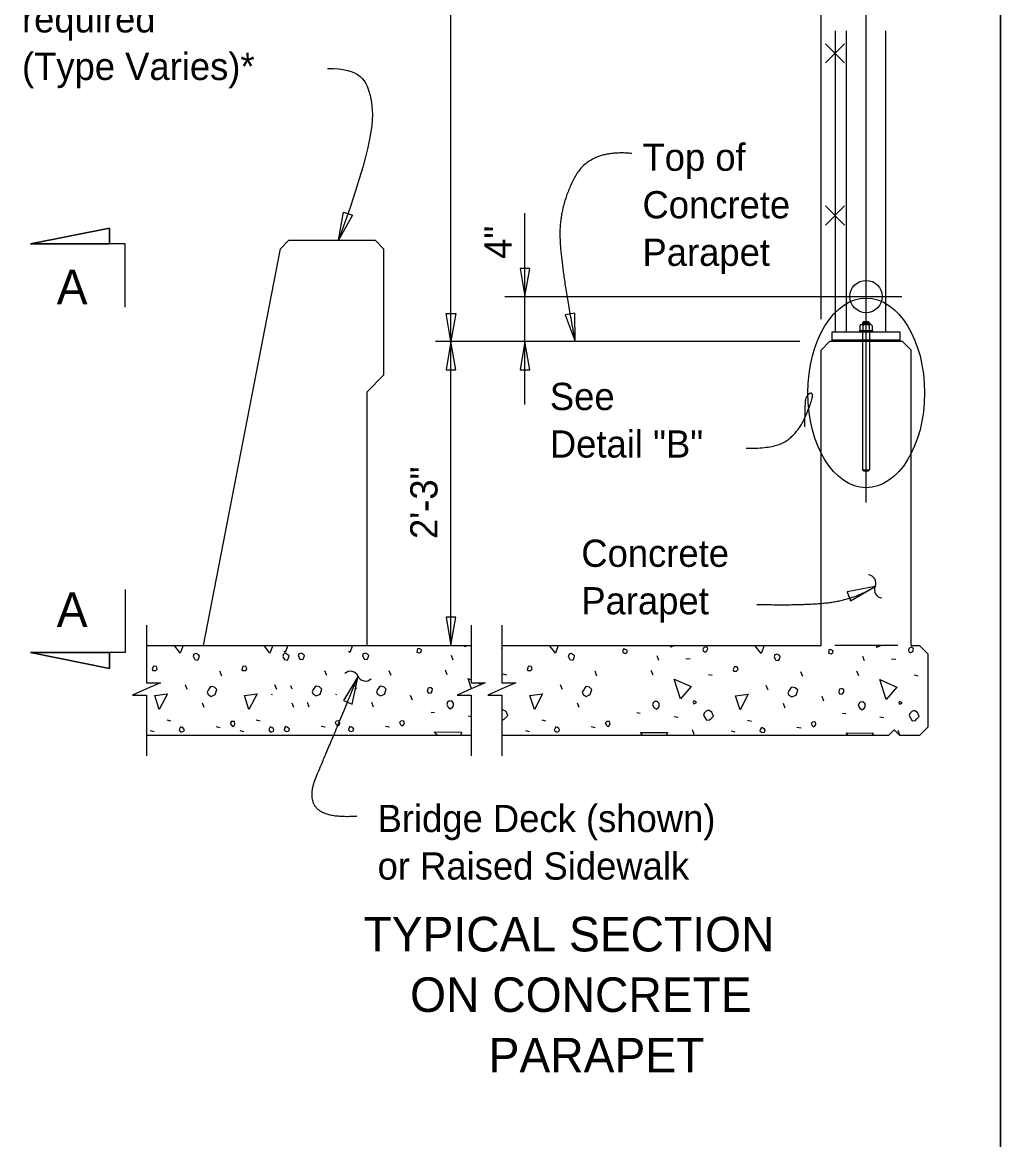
# Model space of a CAD drawing. Extents: x 0 to 41.1, y 0 to 25.9.
# Drawn here: x 33.8 to 41.05, y 10.57 to 18.84 of the extents above; entities that cross this region are included whole.
import ezdxf

# ---------------------------------------------------------------- set-up
doc = ezdxf.new("R2010")
doc.units = 0
for name, color, linetype in [('ActivePts-ConstElements', 7, 'Continuous'), ('CL_Major', 7, 'Continuous'), ('Dimension', 7, 'Continuous'), ('Miscellaneous', 7, 'Continuous'), ('Miscellaneous1', 7, 'Continuous'), ('SteelMisc', 7, 'Continuous'), ('SteelMisc_h', 7, 'Continuous'), ('SupstrConc', 7, 'Continuous'), ('SupstrConc_h', 7, 'Continuous'), ('TextStructures', 7, 'Continuous')]:
    doc.layers.add(name, color=color, linetype=linetype)

# ---------------------------------------------------------------- blocks, each defined once
blk = doc.blocks.new('Terminator-Arrow')
at = {"layer": 'Dimension'}
blk.add_lwpolyline([(0, 0), (-0.00041, 0.000069), (-0.00041, -0.000069), (0, 0)], dxfattribs=at)
blk.add_lwpolyline([(0, 0), (-0.00041, 0.000069), (-0.00041, -0.000069)], close=True, dxfattribs=at)

msp = doc.modelspace()

# ---------------------------------------------------------------- linework, layer by layer
at = {"layer": 'ActivePts-ConstElements'}
msp.add_lwpolyline([(0, 0), (41.0506, 0), (41.0506, 25.9461), (0, 25.9461)], close=True, dxfattribs=at)
at = {"layer": 'CL_Major'}
for p, q in [((40.0537, 15.2829), (40.0537, 19.5023)), ((37.3776, 16.8078), (40.3194, 16.8078))]:
    msp.add_line(p, q, dxfattribs=at)
at = {"layer": 'Dimension'}
for p, q in [((36.9797, 14.2246), (36.9797, 22.8079)), ((39.7204, 16.6402), (39.7204, 19.0859)), ((37.5276, 16.0092), (37.5276, 17.4261)), ((33.8643, 17.1974), (34.4503, 17.3146)), ((34.4503, 17.3146), (34.4503, 17.1974)), ((34.5675, 17.1974), (33.8643, 17.1974)), ((34.5675, 16.7286), (34.5675, 17.1974)), ((40.0537, 16.5552), (40.0537, 16.5545)), ((39.5643, 16.4746), (36.8659, 16.4746)), ((34.5675, 14.6399), (34.5675, 14.1711)), ((34.5675, 14.1711), (33.8643, 14.1711)), ((33.8643, 14.1711), (34.4503, 14.0539)), ((34.4503, 14.0539), (34.4503, 14.1711))]:
    msp.add_line(p, q, dxfattribs=at)
for points in [[(34.4503, 17.1974), (34.4503, 17.3146), (33.8643, 17.1974)], [(37.5276, 16.8079), (37.5629, 17.0161), (37.4923, 17.0161)], [(36.9797, 16.4746), (36.9444, 16.6828), (37.015, 16.6828)], [(37.8983, 16.4746), (37.8958, 16.6858), (37.8263, 16.6731)], [(36.9797, 16.4746), (36.9444, 16.2663), (37.015, 16.2663)], [(37.5276, 16.4746), (37.4923, 16.2663), (37.5629, 16.2663)], [(40.1214, 14.6607), (39.9139, 14.6211), (39.9386, 14.5549)], [(36.9797, 14.2246), (37.015, 14.4328), (36.9444, 14.4328)], [(34.4503, 14.1711), (34.4503, 14.0539), (33.8643, 14.1711)], [(36.2916, 13.9969), (36.1831, 13.8157), (36.2488, 13.79)]]:
    msp.add_lwpolyline(points, close=True, dxfattribs=at)
for points in [[(34.7238, 14.3746), (34.7238, 13.9474), (34.8272, 13.9474), (34.7238, 13.9024), (34.6205, 13.8574), (34.7238, 13.8574), (34.7238, 13.4079)], [(37.1296, 14.3746), (37.1296, 13.9474), (37.233, 13.9474), (37.1296, 13.9024), (37.0263, 13.8574), (37.1296, 13.8574), (37.1296, 13.4079)], [(37.3569, 14.3746), (37.3569, 13.9474), (37.4602, 13.9474), (37.3569, 13.9024), (37.2536, 13.8574), (37.3569, 13.8574), (37.3569, 13.4079)]]:
    msp.add_lwpolyline(points, dxfattribs=at)
for centre, start, end in [((40.0672, 14.6869), 334.61622, 86.34344), ((40.1749, 14.6358), 154.61622, 266.34344), ((36.236, 13.9739), 22.88008, 134.6073), ((36.3458, 14.0202), 202.88008, 314.6073)]:
    msp.add_arc(centre, 0.0596, start, end, dxfattribs=at)
msp.add_ellipse((40.055, 16.0943), major_axis=(0, 0.7024), ratio=0.61552, dxfattribs=at)
for points, degree in [([(36.0647, 18.496), (36.3065, 18.5019), (36.4127, 18.3129), (36.4127, 17.9586), (36.1473, 17.2245)], 3), ([(38.3183, 17.8669), (38.0045, 17.8975), (37.7862, 17.4818), (37.7862, 17.0625), (37.8983, 16.4745)], 2), ([(39.1649, 15.6846), (39.3915, 15.6806), (39.562, 15.8155), (39.6571, 16.0457), (39.6571, 16.0974), (39.6199, 16.0825), (39.5976, 16.0298), (39.599, 15.843)], 2), ([(39.246, 14.5284), (39.5846, 14.5201), (39.9562, 14.5615), (40.1214, 14.6607)], 2), ([(36.2826, 12.9596), (36.0506, 12.9429), (35.9147, 13.1019), (36.0652, 13.445), (36.2916, 13.9969)], 2)]:
    msp.add_open_spline(points, degree=degree, dxfattribs=at)
at = {"layer": 'Miscellaneous'}
for p, q in [((39.8952, 18.6785), (39.7538, 18.5373)), ((39.7538, 18.6785), (39.8952, 18.5373)), ((39.8952, 17.4785), (39.7538, 17.3373)), ((39.7538, 17.4785), (39.8952, 17.3373)), ((40.0425, 16.6169), (40.0633, 16.6169)), ((40.0425, 16.6072), (40.0633, 16.6072)), ((39.8037, 16.4815), (40.3037, 16.4815)), ((39.8037, 16.478), (40.3037, 16.478)), ((35.3909, 14.2246), (35.3923, 14.2243)), ((36.9947, 14.1164), (36.9824, 14.15)), ((38.169, 14.2246), (38.1703, 14.2243)), ((38.5186, 14.1129), (38.5062, 14.1465)), ((39.6751, 14.2246), (39.6941, 14.2207)), ((38.7183, 14.1288), (38.7501, 14.1253)), ((40.0424, 14.1094), (40.03, 14.143)), ((40.2421, 14.1253), (40.274, 14.1218)), ((35.2827, 13.998), (35.2685, 14.0334)), ((36.0602, 14.0015), (36.0461, 14.0369)), ((36.5369, 14.0015), (36.5228, 14.0369)), ((36.9523, 14.0068), (36.9382, 14.0422)), ((37.3624, 14.0139), (37.3907, 14.0068)), ((38.0607, 13.998), (38.0466, 14.0334)), ((38.4761, 14.0033), (38.462, 14.0387)), ((38.8863, 14.0104), (38.9145, 14.0033)), ((39.5845, 13.9945), (39.5704, 14.0298)), ((39.9999, 13.9998), (39.9858, 14.0351)), ((40.4101, 14.0068), (40.4384, 13.9998)), ((35.0263, 13.8972), (35.0122, 13.9326)), ((35.6898, 13.8972), (35.6757, 13.9326)), ((35.8039, 13.9008), (35.7944, 13.9245)), ((36.2806, 13.9008), (36.2711, 13.9245)), ((37.8044, 13.8972), (37.7902, 13.9326)), ((39.3282, 13.8937), (39.3141, 13.9291)), ((36.6942, 13.8195), (36.6801, 13.8548)), ((39.7419, 13.8124), (39.7277, 13.8477)), ((35.1519, 13.7647), (35.1395, 13.7983)), ((35.8154, 13.7647), (35.803, 13.7983)), ((35.9294, 13.7682), (35.917, 13.8018)), ((36.4061, 13.7682), (36.3937, 13.8018)), ((37.9299, 13.7647), (37.9175, 13.7983)), ((39.4537, 13.7611), (39.4413, 13.7947)), ((34.8743, 13.6745), (34.9026, 13.6674)), ((35.5378, 13.6745), (35.5661, 13.6674)), ((36.8321, 13.7311), (36.8569, 13.7275)), ((37.1079, 13.7028), (37.1296, 13.699)), ((37.6524, 13.6745), (37.6806, 13.6674)), ((38.3559, 13.7275), (38.3807, 13.724)), ((38.6317, 13.6993), (38.6617, 13.694)), ((39.1762, 13.671), (39.2045, 13.6639)), ((39.8797, 13.724), (39.9045, 13.7205)), ((40.1555, 13.6957), (40.1856, 13.6904)), ((34.7523, 13.595), (34.7806, 13.5879)), ((35.2402, 13.6232), (35.2703, 13.6179)), ((35.4158, 13.595), (35.4441, 13.5879)), ((36.0178, 13.6268), (36.0478, 13.6215)), ((36.4945, 13.6268), (36.5245, 13.6215)), ((37.5304, 13.595), (37.5587, 13.5879)), ((38.0183, 13.6232), (38.0483, 13.6179)), ((38.7802, 13.5649), (38.7678, 13.5985)), ((39.0542, 13.5914), (39.0825, 13.5844)), ((39.5421, 13.6197), (39.5721, 13.6144)), ((40.304, 13.5614), (40.2916, 13.595))]:
    msp.add_line(p, q, dxfattribs=at)
for points in [[(39.8246, 18.7753), (39.8246, 16.5475)], [(34.9751, 14.1677), (34.9319, 14.2246)], [(34.9963, 14.2246), (34.9751, 14.1677)], [(35.0741, 14.1359), (35.0829, 14.12), (35.1041, 14.1164), (35.113, 14.1324), (35.1165, 14.1465), (35.1077, 14.1553), (35.0918, 14.1642), (35.0758, 14.1589), (35.0705, 14.143), (35.0741, 14.1359)], [(35.6386, 14.1677), (35.5954, 14.2246)], [(35.6598, 14.2246), (35.6386, 14.1677)], [(35.7376, 14.1359), (35.7464, 14.12), (35.7676, 14.1164), (35.7765, 14.1324), (35.78, 14.1465), (35.7712, 14.1553), (35.7553, 14.1642), (35.7393, 14.1589), (35.734, 14.143), (35.7376, 14.1359)], [(35.7526, 14.1713), (35.7438, 14.1829)], [(35.7725, 14.2246), (35.7526, 14.1713)], [(35.8516, 14.1394), (35.8605, 14.1235), (35.8817, 14.12), (35.8905, 14.1359), (35.894, 14.15), (35.8852, 14.1589), (35.8693, 14.1677), (35.8534, 14.1624), (35.8481, 14.1465), (35.8516, 14.1394)], [(36.2293, 14.1713), (36.2205, 14.1829)], [(36.2492, 14.2246), (36.2293, 14.1713)], [(36.3283, 14.1394), (36.3371, 14.1235), (36.3584, 14.12), (36.3672, 14.1359), (36.3707, 14.15), (36.3619, 14.1589), (36.346, 14.1677), (36.3301, 14.1624), (36.3248, 14.1465), (36.3283, 14.1394)], [(36.7278, 14.1748), (36.7473, 14.1695), (36.7596, 14.1783), (36.7614, 14.1907), (36.7579, 14.1942), (36.7437, 14.2013), (36.7314, 14.1995), (36.7296, 14.1872), (36.7278, 14.1748)], [(37.0831, 14.2154), (37.0859, 14.2246)], [(37.1034, 14.2246), (37.0831, 14.2154)], [(37.3569, 14.2024), (37.3571, 14.2031), (37.3569, 14.2043)], [(37.7531, 14.1677), (37.7099, 14.2246)], [(37.7744, 14.2246), (37.7531, 14.1677)], [(37.8521, 14.1359), (37.861, 14.12), (37.8822, 14.1164), (37.891, 14.1324), (37.8945, 14.1465), (37.8857, 14.1553), (37.8698, 14.1642), (37.8539, 14.1589), (37.8486, 14.143), (37.8521, 14.1359)], [(38.2516, 14.1713), (38.2711, 14.1659), (38.2834, 14.1748), (38.2852, 14.1872), (38.2817, 14.1907), (38.2675, 14.1978), (38.2552, 14.196), (38.2534, 14.1836), (38.2516, 14.1713)], [(38.6069, 14.2119), (38.6108, 14.2246)], [(38.6351, 14.2246), (38.6069, 14.2119)], [(38.8544, 14.1766), (38.8615, 14.1766), (38.8756, 14.1836), (38.881, 14.1995), (38.8792, 14.2084), (38.865, 14.2154), (38.8474, 14.2048), (38.8438, 14.1942), (38.8474, 14.1836), (38.8544, 14.1766)], [(39.2769, 14.1642), (39.231, 14.2246)], [(39.2995, 14.2246), (39.2769, 14.1642)], [(39.3759, 14.1324), (39.3848, 14.1164), (39.406, 14.1129), (39.4148, 14.1288), (39.4184, 14.143), (39.4095, 14.1518), (39.3936, 14.1606), (39.3777, 14.1553), (39.3724, 14.1394), (39.3759, 14.1324)], [(39.7754, 14.1677), (39.7949, 14.1624), (39.8073, 14.1713), (39.809, 14.1836), (39.8055, 14.1872), (39.7914, 14.1942), (39.779, 14.1925), (39.7772, 14.1801), (39.7754, 14.1677)], [(40.1308, 14.2084), (40.1357, 14.2246)], [(40.1668, 14.2246), (40.1308, 14.2084)], [(40.3782, 14.173), (40.3853, 14.173), (40.3995, 14.1801), (40.4048, 14.196), (40.403, 14.2048), (40.3889, 14.2119), (40.3712, 14.2013), (40.3676, 14.1907), (40.3712, 14.1801), (40.3782, 14.173)], [(34.7718, 14.0387), (34.793, 14.0387), (34.8036, 14.0493), (34.7983, 14.0687), (34.7753, 14.0705), (34.7718, 14.0599), (34.7665, 14.051), (34.7718, 14.0387), (34.7683, 14.0422)], [(35.4353, 14.0387), (35.4565, 14.0387), (35.4671, 14.0493), (35.4618, 14.0687), (35.4388, 14.0705), (35.4353, 14.0599), (35.43, 14.051), (35.4353, 14.0387), (35.4318, 14.0422)], [(37.5498, 14.0387), (37.571, 14.0387), (37.5816, 14.0493), (37.5763, 14.0687), (37.5534, 14.0705), (37.5498, 14.0599), (37.5445, 14.051), (37.5498, 14.0387), (37.5463, 14.0422)], [(39.0736, 14.0351), (39.0949, 14.0351), (39.1055, 14.0457), (39.1002, 14.0652), (39.0772, 14.067), (39.0736, 14.0563), (39.0683, 14.0475), (39.0736, 14.0351), (39.0701, 14.0387)], [(35.1801, 13.8601), (35.2031, 13.8477), (35.2332, 13.8601), (35.2455, 13.8972), (35.2279, 13.9149), (35.2049, 13.9202), (35.1943, 13.9132), (35.1819, 13.8937), (35.1731, 13.8778), (35.1801, 13.8601)], [(35.9577, 13.8637), (35.9807, 13.8513), (36.0107, 13.8637), (36.0231, 13.9008), (36.0054, 13.9185), (35.9824, 13.9238), (35.9718, 13.9167), (35.9594, 13.8972), (35.9506, 13.8813), (35.9577, 13.8637)], [(36.4344, 13.8637), (36.4573, 13.8513), (36.4874, 13.8637), (36.4998, 13.9008), (36.4821, 13.9185), (36.4591, 13.9238), (36.4485, 13.9167), (36.4361, 13.8972), (36.4273, 13.8813), (36.4344, 13.8637)], [(36.8038, 13.8866), (36.8127, 13.8707), (36.8321, 13.8725), (36.841, 13.8849), (36.8427, 13.9043), (36.8303, 13.9096), (36.8215, 13.9114), (36.8109, 13.9079), (36.8074, 13.9043), (36.8038, 13.8866)], [(37.1323, 13.9036), (37.1079, 13.9786), (37.1296, 13.9691)], [(37.1792, 13.9474), (37.206, 13.9357)], [(37.9582, 13.8601), (37.9812, 13.8477), (38.0112, 13.8601), (38.0236, 13.8972), (38.0059, 13.9149), (37.9829, 13.9202), (37.9723, 13.9132), (37.9599, 13.8937), (37.9511, 13.8778), (37.9582, 13.8601)], [(38.6794, 13.8283), (38.6317, 13.975), (38.7572, 13.9202), (38.6794, 13.8283)], [(39.482, 13.8566), (39.505, 13.8442), (39.535, 13.8566), (39.5474, 13.8937), (39.5297, 13.9114), (39.5067, 13.9167), (39.4961, 13.9096), (39.4838, 13.8902), (39.4749, 13.8743), (39.482, 13.8566)], [(39.8515, 13.8796), (39.8603, 13.8637), (39.8797, 13.8654), (39.8886, 13.8778), (39.8903, 13.8972), (39.878, 13.9025), (39.8691, 13.9043), (39.8585, 13.9008), (39.855, 13.8972), (39.8515, 13.8796)], [(40.2032, 13.8248), (40.1555, 13.9715), (40.281, 13.9167), (40.2032, 13.8248)], [(34.8195, 13.7505), (34.7859, 13.8548), (34.8796, 13.8672), (34.8195, 13.7505)], [(35.483, 13.7505), (35.4494, 13.8548), (35.5431, 13.8672), (35.483, 13.7505)], [(35.6532, 13.863), (35.6503, 13.8574)], [(36.1298, 13.863), (36.127, 13.8574)], [(37.5976, 13.7505), (37.564, 13.8548), (37.6577, 13.8672), (37.5976, 13.7505)], [(39.1214, 13.747), (39.0878, 13.8513), (39.1815, 13.8637), (39.1214, 13.747)], [(36.9488, 13.7876), (36.9594, 13.7664), (36.9771, 13.7558), (36.9912, 13.7664), (36.9983, 13.777), (36.9983, 13.7983), (36.9824, 13.8142), (36.9629, 13.8124), (36.9541, 13.8036), (36.9488, 13.7876)], [(37.3569, 13.6752), (37.3713, 13.6763), (37.3801, 13.6851), (37.3996, 13.7046), (37.3872, 13.7346), (37.3624, 13.7488), (37.3569, 13.7465)], [(38.4726, 13.7841), (38.4832, 13.7629), (38.5009, 13.7523), (38.515, 13.7629), (38.5221, 13.7735), (38.5221, 13.7947), (38.5062, 13.8106), (38.4867, 13.8089), (38.4779, 13.8), (38.4726, 13.7841)], [(38.7784, 13.7929), (38.7979, 13.8018), (38.7908, 13.8089), (38.7784, 13.8142), (38.7731, 13.8018), (38.7784, 13.7929)], [(38.8491, 13.7081), (38.8721, 13.671), (38.8951, 13.6727), (38.9039, 13.6816), (38.9234, 13.701), (38.911, 13.7311), (38.8863, 13.7452), (38.8686, 13.7381), (38.8544, 13.724), (38.8491, 13.7081)], [(39.9964, 13.7806), (40.007, 13.7594), (40.0247, 13.7488), (40.0388, 13.7594), (40.0459, 13.77), (40.0459, 13.7912), (40.03, 13.8071), (40.0106, 13.8053), (40.0017, 13.7965), (39.9964, 13.7806)], [(40.3022, 13.7894), (40.3217, 13.7983), (40.3146, 13.8053), (40.3022, 13.8106), (40.2969, 13.7983), (40.3022, 13.7894)], [(40.3729, 13.7046), (40.3959, 13.6674), (40.4189, 13.6692), (40.4277, 13.678), (40.4472, 13.6975), (40.4348, 13.7275), (40.4101, 13.7417), (40.3924, 13.7346), (40.3782, 13.7205), (40.3729, 13.7046)], [(35.3516, 13.6356), (35.3622, 13.625), (35.3728, 13.6321), (35.3799, 13.6427), (35.3764, 13.6604), (35.3675, 13.6621), (35.3551, 13.6604), (35.3445, 13.6498), (35.3516, 13.6356)], [(36.1292, 13.6392), (36.1398, 13.6285), (36.1504, 13.6356), (36.1574, 13.6462), (36.1539, 13.6639), (36.1451, 13.6657), (36.1327, 13.6639), (36.1221, 13.6533), (36.1292, 13.6392)], [(36.6058, 13.6392), (36.6164, 13.6285), (36.6271, 13.6356), (36.6341, 13.6462), (36.6306, 13.6639), (36.6218, 13.6657), (36.6094, 13.6639), (36.5988, 13.6533), (36.6058, 13.6392)], [(38.1297, 13.6356), (38.1403, 13.625), (38.1509, 13.6321), (38.1579, 13.6427), (38.1544, 13.6604), (38.1456, 13.6621), (38.1332, 13.6604), (38.1226, 13.6498), (38.1297, 13.6356)], [(39.6535, 13.6321), (39.6641, 13.6215), (39.6747, 13.6285), (39.6817, 13.6392), (39.6782, 13.6568), (39.6694, 13.6586), (39.657, 13.6568), (39.6464, 13.6462), (39.6535, 13.6321)], [(34.9768, 13.5861), (34.9892, 13.5844), (35.0016, 13.5897), (35.0051, 13.6003), (34.9998, 13.6091), (34.9892, 13.6162), (34.9768, 13.6215), (34.9698, 13.6073), (34.9662, 13.5967), (34.9768, 13.5861)], [(35.6403, 13.5861), (35.6527, 13.5844), (35.6651, 13.5897), (35.6686, 13.6003), (35.6633, 13.6091), (35.6527, 13.6162), (35.6403, 13.6215), (35.6333, 13.6073), (35.6297, 13.5967), (35.6403, 13.5861)], [(35.7544, 13.5897), (35.7668, 13.5879), (35.7791, 13.5932), (35.7827, 13.6038), (35.7774, 13.6126), (35.7668, 13.6197), (35.7544, 13.625), (35.7473, 13.6109), (35.7438, 13.6003)], [(35.7438, 13.6003), (35.7544, 13.5897)], [(36.2311, 13.5897), (36.2434, 13.5879), (36.2558, 13.5932), (36.2594, 13.6038), (36.2541, 13.6126), (36.2434, 13.6197), (36.2311, 13.625), (36.224, 13.6109), (36.2205, 13.6003)], [(36.2205, 13.6003), (36.2311, 13.5897)], [(36.8788, 13.5578), (36.8586, 13.5844), (37.0584, 13.5826), (37.0491, 13.5578)], [(37.7549, 13.5861), (37.7673, 13.5844), (37.7796, 13.5897), (37.7832, 13.6003), (37.7779, 13.6091), (37.7673, 13.6162), (37.7549, 13.6215), (37.7478, 13.6073), (37.7443, 13.5967), (37.7549, 13.5861)], [(38.3999, 13.5578), (38.3824, 13.5808), (38.5822, 13.579), (38.5743, 13.5578)], [(39.2787, 13.5826), (39.2911, 13.5808), (39.3034, 13.5861), (39.307, 13.5967), (39.3017, 13.6056), (39.2911, 13.6126), (39.2787, 13.6179), (39.2716, 13.6038), (39.2681, 13.5932), (39.2787, 13.5826)], [(39.921, 13.5578), (39.9063, 13.5773), (40.106, 13.5755), (40.0994, 13.5578)]]:
    msp.add_lwpolyline(points, dxfattribs=at)
msp.add_lwpolyline([(39.8037, 16.485), (40.3037, 16.485), (40.3037, 16.4745), (39.8037, 16.4745)], close=True, dxfattribs=at)
at = {"layer": 'Miscellaneous1'}
msp.add_lwpolyline([(0, 25.9461), (41.0506, 25.9461), (41.0506, 0), (0, 0)], close=True, dxfattribs=at)
at = {"layer": 'SteelMisc'}
for p, q in [((39.9079, 16.5475), (39.9079, 18.7753)), ((40.1996, 16.5475), (40.1996, 18.7753)), ((40.0041, 16.5545), (40.0041, 16.5474)), ((40.0041, 16.5545), (40.1035, 16.5545)), ((40.0083, 16.5921), (40.0083, 16.5545)), ((40.0991, 16.5545), (40.0083, 16.5545)), ((40.0878, 16.6008), (40.0197, 16.6008)), ((40.0376, 16.6218), (40.028, 16.6121)), ((40.028, 16.6121), (40.028, 16.6008)), ((40.028, 16.6121), (40.0795, 16.6121)), ((40.031, 16.5924), (40.031, 16.5545)), ((40.0376, 16.6218), (40.0682, 16.6218)), ((40.0682, 16.6218), (40.0795, 16.6121)), ((40.0764, 16.5924), (40.0764, 16.5545)), ((40.0795, 16.6121), (40.0795, 16.6008)), ((40.0991, 16.5921), (40.0991, 16.5545)), ((40.1035, 16.5545), (40.1035, 16.5474)), ((39.9339, 16.485), (40.1735, 16.485))]:
    msp.add_line(p, q, dxfattribs=at)
msp.add_lwpolyline([(39.8037, 16.5475), (40.3037, 16.5475), (40.3037, 16.485), (39.8037, 16.485)], close=True, dxfattribs=at)
msp.add_circle((40.0537, 16.8078), 0.1198, dxfattribs=at)
for centre, radius, start, end in [((40.0197, 16.589), 0.0118, 16.59863, 164.70054), ((40.0537, 16.5661), 0.0347, 49.20147, 130.79853), ((40.0877, 16.5891), 0.0118, 15.15064, 163.50417)]:
    msp.add_arc(centre, radius, start, end, dxfattribs=at)
at = {"layer": 'SteelMisc_h'}
for p, q in [((40.0277, 16.5475), (40.0277, 15.5243)), ((40.0798, 16.5475), (40.0798, 15.5243)), ((40.0277, 15.5243), (40.0798, 15.5243)), ((40.0277, 15.5243), (40.0359, 15.5162)), ((40.0359, 15.5162), (40.0716, 15.5162)), ((40.0798, 15.5243), (40.0716, 15.5162))]:
    msp.add_line(p, q, dxfattribs=at)
at = {"layer": 'SupstrConc'}
for p, q in [((39.7829, 16.4745), (39.7204, 16.4112)), ((40.3245, 16.4745), (39.7829, 16.4745)), ((40.3245, 16.4745), (39.7829, 16.4745)), ((40.3245, 16.4745), (40.3871, 16.4112)), ((39.7204, 14.2246), (39.7204, 16.4112)), ((40.3871, 14.2246), (40.3871, 16.4112)), ((34.7238, 14.2246), (37.1296, 14.2246)), ((37.3569, 14.2246), (39.7204, 14.2246)), ((40.3871, 14.2246), (40.4496, 14.2246)), ((40.4496, 14.2246), (40.5121, 14.1621)), ((40.5121, 14.1621), (40.5121, 13.6204)), ((40.2204, 13.5579), (40.2621, 13.5995)), ((40.2621, 13.5995), (40.3037, 13.5579)), ((40.5121, 13.6204), (40.4496, 13.5579)), ((40.2204, 13.5579), (37.3569, 13.5579)), ((40.4496, 13.5579), (40.3037, 13.5579))]:
    msp.add_line(p, q, dxfattribs=at)
at = {"layer": 'SupstrConc_h'}
for p, q in [((35.7163, 17.162), (35.7788, 17.2245)), ((35.7788, 17.2245), (36.4178, 17.2246)), ((36.4178, 17.2245), (36.4803, 17.162)), ((35.147, 14.2246), (35.7163, 17.162)), ((36.4803, 17.162), (36.4803, 16.2245)), ((36.4803, 16.2245), (36.3553, 16.0995)), ((36.3553, 16.0995), (36.3553, 14.2246)), ((40.2885, 14.2246), (39.8234, 14.2246)), ((37.1296, 13.5579), (34.7238, 13.5579))]:
    msp.add_line(p, q, dxfattribs=at)

# ---------------------------------------------------------------- block references
at = {"layer": 'Dimension', "xscale": 507.9999699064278, "yscale": -507.99996990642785, "rotation": -109.44616743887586}
msp.add_blockref('Terminator-Arrow', (36.1473, 17.2245), dxfattribs=at)

# ---------------------------------------------------------------- texts
at = {"layer": 'Dimension'}
for s, height, p in [('required', 0.2016, (33.8024, 18.763)), ('(Type Varies)*', 0.2016, (33.8024, 18.411)), ('Top of ', 0.2016, (38.3979, 17.7388)), ('Concrete', 0.2016, (38.3979, 17.3868)), ('Parapet', 0.2016, (38.3979, 17.0348)), ('See ', 0.2016, (37.7119, 15.9673)), ('Detail "B"', 0.2016, (37.7119, 15.6153)), ('Concrete', 0.2016, (37.9448, 14.8065)), ('Parapet', 0.2016, (37.9448, 14.4545)), ('Bridge Deck (shown)', 0.2016, (36.4361, 12.8428)), ('or Raised Sidewalk', 0.2016, (36.4361, 12.4908)), ('TYPICAL SECTION', 0.256001, (36.3315, 11.9589)), ('ON CONCRETE', 0.256001, (36.6769, 11.5109)), ('PARAPET', 0.256, (37.2584, 11.0629))]:
    msp.add_text(s, height=height, dxfattribs=at).set_placement(p)
at = {"layer": 'TextStructures'}
for s, p in [('4"', (37.4279, 17.0864)), ('2\'-3"', (36.8797, 15.0126))]:
    msp.add_text(s, height=0.2016, rotation=90, dxfattribs=at).set_placement(p)
for p in [(34.0596, 16.7507), (34.0596, 14.362)]:
    msp.add_text('A', height=0.256, dxfattribs=at).set_placement(p)

doc.saveas('drawing.dxf')
